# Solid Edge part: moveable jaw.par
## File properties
Title: Moveable Jaw
Author: Robert a Rhodes jr
Template: Normal.par
Last saved by: Rajat Kamboj
Revision: 20
Application: Solid Edge
Accuracy: 0.99
Material: iron
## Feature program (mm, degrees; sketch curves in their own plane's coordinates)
sketch for "unnamed Protrusion 1" plane through (0, 0, 0) normal (0, -1, 0) x-axis (1, 0, 0)
  line (-36.5256, 25.2528) -> (-36.5256, -34.7472)
  line (-36.5256, -34.7472) -> (-33.0256, -34.7472)
  line (-33.0256, -34.7472) -> (-33.0256, -32.2472)
  line (-33.0256, -32.2472) -> (-30.5256, -32.2472)
  line (-30.5256, -32.2472) -> (-30.5256, -29.7472)
  line (-30.5256, -29.7472) -> (-28.0256, -29.7472)
  line (-28.0256, -29.7472) -> (-28.0256, -27.2472)
  line (-28.0256, -27.2472) -> (-25.5256, -27.2472)
  line (-25.5256, -27.2472) -> (-25.5256, -24.7472)
  line (-25.5256, -24.7472) -> (-23.0256, -24.7472)
  line (-23.0256, -24.7472) -> (-23.0256, -22.2472)
  line (-23.0256, -22.2472) -> (-20.5256, -22.2472)
  line (-20.5256, -22.2472) -> (-20.5256, -19.7472)
  line (-20.5256, -19.7472) -> (-18.0256, -19.7472)
  line (-18.0256, -22.2472) -> (-18.0256, -19.7472)
  line (-15.5256, -22.2472) -> (-18.0256, -22.2472)
  line (-15.5256, -24.7472) -> (-15.5256, -22.2472)
  line (-13.0256, -24.7472) -> (-15.5256, -24.7472)
  line (-13.0256, -27.2472) -> (-13.0256, -24.7472)
  line (-10.5256, -27.2472) -> (-13.0256, -27.2472)
  line (-10.5256, -29.7472) -> (-10.5256, -27.2472)
  line (-8.0256, -29.7472) -> (-10.5256, -29.7472)
  line (-8.0256, -32.2472) -> (-8.0256, -29.7472)
  line (-5.5256, -32.2472) -> (-8.0256, -32.2472)
  line (-5.5256, -34.7472) -> (-5.5256, -32.2472)
  line (-2.0256, -34.7472) -> (-5.5256, -34.7472)
  line (-2.0256, -34.7472) -> (-2.0256, 25.2528)
  line (-2.0256, 25.2528) -> (-36.5256, 25.2528)
extrude "unnamed Protrusion 1" add finite 18 along -normal
sketch for "Hole_1" plane through (-19.2756, 9, 25.2528) normal (0, 0, 1) x-axis (1, 0, 0)
  hole centre (0, 0) bore radius 6
hole "Hole_1" diameter 12 finite  VBottomAngle = 118 deg
sketch for "Hole_2" plane through (-2.0256, 9, -4.7472) normal (1, 0, 0) x-axis (0, 1, 0)
  hole centre (0, 23) bore radius 4.5
hole "Hole_2" diameter 9 through
chamfer "Chamfer_1" setback 2
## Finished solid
Body 1: solid body, 38 faces, 98 edges, 60 vertices.
  Faces by surface: plane 34, cylinder 3, cone 1
  Edges by curve: line 92, circle 4, intersection 2
Bounding box of the edges (mm): 34.500 x 18.000 x 60.000, from (-36.5256, 0, -34.7472) to (-2.0256, 18, 25.2528).
Cylindrical faces by radius (mm): R4.5 x2, R6 x1
Conical faces (half-angle, radius in mm at the cone's reference point): 59 deg R6 x1
Planar faces by outward normal: +x 7, +y 1, +z 1, -x 7, -y 1, -z 13, oblique 4
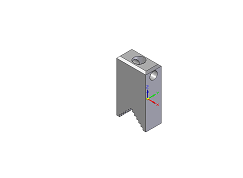
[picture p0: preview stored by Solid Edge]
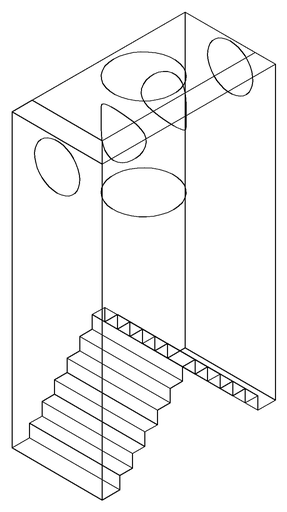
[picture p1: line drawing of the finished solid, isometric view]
